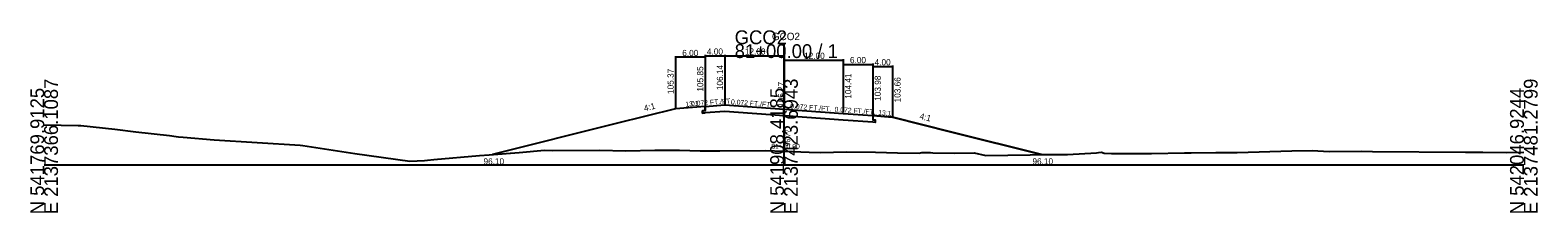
# Model space of a CAD drawing. Extents: x -14327 to 8886, y -10 to 39048.
# Drawn here: x 2997.2 to 3302.8, y 21990.3 to 22027.3 of the extents above; entities that cross this region are included whole.
import ezdxf

# ---------------------------------------------------------------- set-up
doc = ezdxf.new("R2010")
doc.units = 0
for name, color, linetype in [('Level 5', 7, 'Continuous'), ('Level 53', 7, 'Continuous'), ('Level 54', 7, 'Continuous'), ('Level 55', 7, 'Continuous'), ('Level 7', 7, 'Continuous'), ('RD_GPK_XS_Cell', 7, 'Continuous'), ('RD_XS_EwShp', 7, 'Continuous'), ('RD_XS_ExGround', 7, 'Continuous'), ('RD_XS_Pave', 7, 'Continuous'), ('RD_XS_TX_Baseline', 7, 'Continuous'), ('RD_XS_TX_Elev_EX', 7, 'Continuous'), ('RD_XS_TX_Elev_PR', 7, 'Continuous'), ('RD_XS_TX_Station', 7, 'Continuous')]:
    doc.layers.add(name, color=color, linetype=linetype)

msp = doc.modelspace()

# ---------------------------------------------------------------- linework, layer by layer
at = {"layer": 'Level 5'}
for p, q in [((3134, 22011.02), (3133.5, 22010.98)), ((3133.5, 22010.98), (3133.5, 22010.48)), ((3133.5, 22010.48), (3134, 22010.52)), ((3134, 22011.85), (3134, 22011.02)), ((3138, 22010.8), (3134, 22010.52)), ((3150, 22009.94), (3138, 22010.8)), ((3162, 22009.08), (3150, 22009.94)), ((3168, 22008.64), (3162, 22009.08)), ((3168, 22009.98), (3168, 22009.14)), ((3168, 22009.14), (3168.5, 22009.11)), ((3168.5, 22009.11), (3168.5, 22008.61)), ((3168.5, 22008.61), (3168, 22008.64))]:
    msp.add_line(p, q, dxfattribs=at)
at = {"layer": 'Level 54'}
for p, q in [((3128, 22022), (3128, 22011.57)), ((3134, 22021.8), (3128, 22021.8)), ((3134, 22022.29), (3134, 22012.05)), ((3134, 22022.09), (3138, 22022.09)), ((3134, 22022), (3134, 22012.05)), ((3138, 22022.29), (3138, 22012.34)), ((3138, 22022.09), (3150, 22022.09)), ((3150, 22022.29), (3150, 22011.47)), ((3150, 22021.42), (3150, 22011.47)), ((3162, 22021.42), (3162, 22010.61)), ((3150, 22021.22), (3162, 22021.22)), ((3162, 22020.56), (3162, 22010.61)), ((3162, 22020.36), (3168, 22020.36)), ((3168, 22020.56), (3168, 22010.18)), ((3168, 22020.13), (3168, 22010.18)), ((3168, 22019.93), (3172, 22019.93)), ((3172, 22020.13), (3172, 22009.86))]:
    msp.add_line(p, q, dxfattribs=at)
at = {"layer": 'Level 7'}
for p, q in [((3128, 22011.37), (3116, 22008.37)), ((3134, 22011.85), (3128, 22011.37)), ((3168, 22009.98), (3172, 22009.66)), ((3172, 22009.66), (3184, 22006.66)), ((3116, 22008.37), (3090.93, 22002.1)), ((3184, 22006.66), (3202.22, 22002.1))]:
    msp.add_line(p, q, dxfattribs=at)
at = {"layer": 'RD_GPK_XS_Cell'}
for p, q in [((3150, 22000), (3150, 22024.45)), ((3000, 22000), (3150, 22000)), ((3150, 22000), (3300, 22000))]:
    msp.add_line(p, q, dxfattribs=at)
at = {"layer": 'RD_XS_EwShp'}
msp.add_lwpolyline([(3146.18, 22002.9), (3150, 22002.77), (3155.1, 22002.6), (3157.37, 22002.53), (3162.69, 22002.63), (3168.56, 22002.56), (3173, 22002.43), (3177.4, 22002.39), (3177.92, 22002.53), (3179.72, 22002.53), (3180.19, 22002.48), (3184.49, 22002.4), (3188.56, 22002.47), (3190.95, 22001.94), (3195.36, 22001.97), (3199.9, 22002.08), (3202.14, 22002.1), (3202.22, 22002.1), (3184, 22006.66), (3172, 22009.66), (3168, 22009.98), (3168, 22009.14), (3168.5, 22009.11), (3168.5, 22008.61), (3168, 22008.64), (3162, 22009.08), (3150, 22009.94), (3138, 22010.8), (3134, 22010.52), (3133.5, 22010.48), (3133.5, 22010.98), (3134, 22011.02), (3134, 22011.85), (3128, 22011.37), (3116, 22008.37), (3090.93, 22002.1), (3096.3, 22002.53), (3101.41, 22003), (3103, 22002.95), (3112.6, 22002.96), (3117.95, 22002.85), (3123.79, 22003.02), (3128.79, 22002.98), (3133.01, 22002.83), (3134.98, 22002.84), (3137, 22002.86)], close=True, dxfattribs=at)
at = {"layer": 'RD_XS_ExGround'}
for p, q in [((3000, 22008.15), (3006.9, 22008.01)), ((3006.9, 22008.01), (3007.45, 22008)), ((3007.45, 22008), (3014.32, 22007.26)), ((3014.32, 22007.26), (3018.56, 22006.72)), ((3018.56, 22006.72), (3025.38, 22005.93)), ((3025.38, 22005.93), (3026.76, 22005.79)), ((3026.76, 22005.79), (3027.26, 22005.72)), ((3027.26, 22005.72), (3028.15, 22005.64)), ((3028.15, 22005.64), (3034.5, 22005.1)), ((3034.5, 22005.1), (3051.88, 22004.03)), ((3051.88, 22004.03), (3052.46, 22003.95)), ((3052.46, 22003.95), (3062.99, 22002.3)), ((3096.3, 22002.53), (3101.41, 22003)), ((3101.41, 22003), (3103, 22002.95)), ((3103, 22002.95), (3112.6, 22002.96)), ((3112.6, 22002.96), (3117.95, 22002.85)), ((3117.95, 22002.85), (3123.79, 22003.02)), ((3123.79, 22003.02), (3128.79, 22002.98)), ((3128.79, 22002.98), (3133.01, 22002.83)), ((3062.99, 22002.3), (3074.11, 22000.76)), ((3074.11, 22000.76), (3077.08, 22000.93)), ((3077.08, 22000.93), (3077.73, 22000.94)), ((3077.73, 22000.94), (3078.97, 22001.1)), ((3078.97, 22001.1), (3088.26, 22001.92)), ((3088.26, 22001.92), (3090.21, 22002.05)), ((3090.21, 22002.05), (3096.3, 22002.53)), ((3133.01, 22002.83), (3134.98, 22002.84)), ((3134.98, 22002.84), (3137, 22002.86)), ((3137, 22002.86), (3146.18, 22002.9)), ((3146.18, 22002.9), (3150, 22002.77)), ((3150, 22002.77), (3155.1, 22002.6)), ((3155.1, 22002.6), (3157.37, 22002.53)), ((3157.37, 22002.53), (3162.69, 22002.63)), ((3162.69, 22002.63), (3168.56, 22002.56)), ((3168.56, 22002.56), (3173, 22002.43)), ((3173, 22002.43), (3177.4, 22002.39)), ((3177.4, 22002.39), (3177.92, 22002.53)), ((3177.92, 22002.53), (3179.72, 22002.53)), ((3179.72, 22002.53), (3180.19, 22002.48)), ((3180.19, 22002.48), (3184.49, 22002.4)), ((3184.49, 22002.4), (3188.56, 22002.47)), ((3188.56, 22002.47), (3190.95, 22001.94)), ((3190.95, 22001.94), (3195.36, 22001.97)), ((3195.36, 22001.97), (3199.9, 22002.08)), ((3199.9, 22002.08), (3202.14, 22002.1)), ((3202.14, 22002.1), (3207.48, 22002.12)), ((3207.48, 22002.12), (3213.33, 22002.45)), ((3213.33, 22002.45), (3213.74, 22002.5)), ((3213.74, 22002.5), (3214.4, 22002.57)), ((3214.4, 22002.57), (3214.91, 22002.38)), ((3214.91, 22002.38), (3216.37, 22002.31)), ((3216.37, 22002.31), (3221.35, 22002.35)), ((3221.35, 22002.35), (3222.36, 22002.29)), ((3222.36, 22002.29), (3224.52, 22002.31)), ((3224.52, 22002.31), (3231.22, 22002.43)), ((3231.22, 22002.43), (3232.57, 22002.48)), ((3232.57, 22002.48), (3237.55, 22002.49)), ((3237.55, 22002.49), (3238.35, 22002.51)), ((3238.35, 22002.51), (3241.88, 22002.55)), ((3241.88, 22002.55), (3252.93, 22002.86)), ((3252.93, 22002.86), (3257.07, 22002.91)), ((3257.07, 22002.91), (3260.56, 22002.74)), ((3260.56, 22002.74), (3267.06, 22002.78)), ((3267.06, 22002.78), (3269.29, 22002.72)), ((3269.29, 22002.72), (3288.15, 22002.57)), ((3288.15, 22002.57), (3291.68, 22002.56)), ((3291.68, 22002.56), (3296.56, 22002.55)), ((3296.56, 22002.55), (3300, 22002.59))]:
    msp.add_line(p, q, dxfattribs=at)
at = {"layer": 'RD_XS_Pave'}
for p, q in [((3134, 22011.85), (3138, 22012.14)), ((3138, 22012.14), (3150, 22011.27)), ((3150, 22011.27), (3162, 22010.41)), ((3162, 22010.41), (3168, 22009.98))]:
    msp.add_line(p, q, dxfattribs=at)

# ---------------------------------------------------------------- texts
at = {"layer": 'Level 53'}
for s, rotation, p in [('105.37', 90, (3127.63, 22014.37)), ('105.85', 90, (3133.63, 22014.85)), ('106.14', 90, (3137.63, 22015.14)), ('104.41', 90, (3163.63, 22013.41)), ('103.98', 90, (3169.63, 22012.98)), ('103.66', 90, (3173.63, 22012.66)), ('4:1', 14.0362, (3121.76, 22010.84)), ('4:1', 345.9638, (3177.39, 22009.34))]:
    msp.add_text(s, height=1.25, rotation=rotation, dxfattribs=at).set_placement(p)
for p in [(3089.07, 22000.1), (3200.37, 22000.1)]:
    msp.add_text('96.10', height=1.25, dxfattribs=at).set_placement(p)
at = {"layer": 'Level 54'}
for s, p in [('6.00', (3129.37, 22022.05)), ('4.00', (3134.37, 22022.34)), ('12.00', (3142.07, 22022.34)), ('12.00', (3154.07, 22021.47)), ('6.00', (3163.37, 22020.61)), ('4.00', (3168.37, 22020.18))]:
    msp.add_text(s, height=1.25, dxfattribs=at).set_placement(p)
at = {"layer": 'Level 55'}
for s, rotation, p in [('13:1', 4.5739, (3130.03, 22011.78)), ('0.072 FT./FT.', 4.1182, (3131.18, 22011.9)), ('0.072 FT./FT.', 355.8818, (3139.22, 22012.3)), ('0.072 FT./FT.', 355.8818, (3151.22, 22011.44)), ('0.072 FT./FT.', 355.8818, (3160.22, 22010.79)), ('13:1', 355.4261, (3169.07, 22010.14))]:
    msp.add_text(s, height=1, rotation=rotation, dxfattribs=at).set_placement(p)
at = {"layer": 'RD_GPK_XS_Cell'}
for s, p in [('81+00.00 / 1', (3140, 22021.65)), ('GCO2', (3140, 22024.45))]:
    msp.add_text(s, height=2.8, dxfattribs=at).set_placement(p)
for s, p in [('N 541769.9125', (3000, 21990)), ('E 2137366.1087', (3002.8, 21990)), ('N 541908.4185', (3150, 21990)), ('E 2137423.6943', (3152.8, 21990)), ('N 542046.9244', (3300, 21990)), ('E 2137481.2799', (3302.8, 21990))]:
    msp.add_text(s, height=2.8, rotation=90, dxfattribs=at).set_placement(p)
at = {"layer": 'RD_XS_TX_Baseline'}
msp.add_text('GCO2', height=1.5, dxfattribs=at).set_placement((3147.55, 22025.27))
at = {"layer": 'RD_XS_TX_Elev_EX'}
msp.add_text('96.77', height=1, rotation=90, dxfattribs=at).set_placement((3151.25, 22003.77))
at = {"layer": 'RD_XS_TX_Elev_PR'}
msp.add_text(' 105.27', height=1.25, rotation=90, dxfattribs=at).set_placement((3150, 22011.27))
at = {"layer": 'RD_XS_TX_Station'}
msp.add_text('81+00.00', height=1, dxfattribs=at).set_placement((3147.41, 22003.27))

doc.saveas('drawing.dxf')
